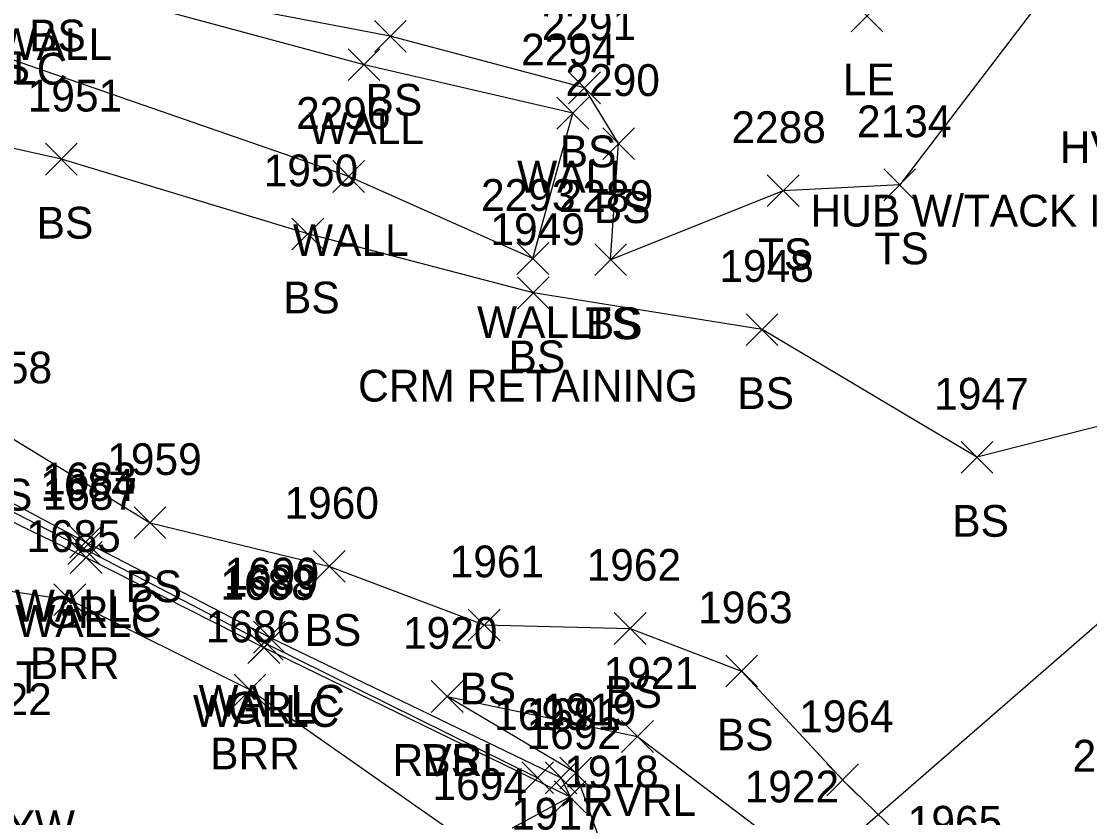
# Model space of a CAD drawing. Extents: x 1647133 to 1649138, y 411736 to 414924.
# Drawn here: x 1648810.3 to 1648877.6, y 412125.5 to 412175.6 of the extents above; entities that cross this region are included whole.
import ezdxf

# ---------------------------------------------------------------- set-up
doc = ezdxf.new("R2010")
doc.units = 0
for name, color, linetype in [('BELB', 7, 'Continuous'), ('C_A', 7, 'Continuous'), ('C_C', 7, 'Continuous'), ('L_A', 7, 'Continuous'), ('L_C', 7, 'Continuous'), ('L_I', 7, 'Continuous'), ('L_TIC', 7, 'Continuous'), ('LABL', 7, 'Continuous'), ('LAWE', 7, 'Continuous'), ('LELB', 7, 'Continuous'), ('LW', 7, 'Continuous'), ('R_A', 7, 'Continuous'), ('R_C', 7, 'Continuous'), ('R_I', 7, 'Continuous'), ('R_TIC', 7, 'Continuous'), ('RGR', 7, 'Continuous'), ('U_A', 7, 'Continuous'), ('U_I', 7, 'Continuous')]:
    doc.layers.add(name, color=color, linetype=linetype)

msp = doc.modelspace()

# ---------------------------------------------------------------- linework, layer by layer
at = {"layer": 'BELB'}
msp.add_lwpolyline([(1648856.366, 412097.638), (1648845.782, 412109.602), (1648891.837, 412149.616), (1648923.124, 412177.419), (1648960.58, 412211.026), (1648974.892, 412224.907)], dxfattribs=at)
at = {"layer": 'L_TIC'}
for points in [[(1648862.557, 412174.929), (1648864.557, 412176.929)], [(1648864.557, 412174.929), (1648862.557, 412176.929)], [(1648832.549, 412173.646), (1648834.549, 412175.646)], [(1648834.549, 412173.646), (1648832.549, 412175.646)], [(1648830.896, 412171.857), (1648832.896, 412173.857)], [(1648832.896, 412171.857), (1648830.896, 412173.857)], [(1648844.777, 412170.401), (1648846.777, 412172.401)], [(1648846.777, 412170.401), (1648844.777, 412172.401)], [(1648844.045, 412168.806), (1648846.045, 412170.806)], [(1648846.045, 412168.806), (1648844.045, 412170.806)], [(1648846.923, 412166.888), (1648848.923, 412168.888)], [(1648848.923, 412166.888), (1648846.923, 412168.888)], [(1648811.843, 412165.91), (1648813.843, 412167.91)], [(1648813.843, 412165.91), (1648811.843, 412167.91)], [(1648829.932, 412164.818), (1648831.932, 412166.818)], [(1648831.932, 412164.818), (1648829.932, 412166.818)], [(1648864.626, 412164.294), (1648866.626, 412166.294)], [(1648866.626, 412164.294), (1648864.626, 412166.294)], [(1648857.285, 412163.924), (1648859.285, 412165.924)], [(1648859.285, 412163.924), (1648857.285, 412165.924)], [(1648827.356, 412161.203), (1648829.356, 412163.203)], [(1648829.356, 412161.203), (1648827.356, 412163.203)], [(1648841.521, 412159.657), (1648843.521, 412161.657)], [(1648843.521, 412159.657), (1648841.521, 412161.657)], [(1648841.521, 412159.657), (1648843.521, 412161.657)], [(1648843.521, 412159.657), (1648841.521, 412161.657)], [(1648846.42, 412159.585), (1648848.42, 412161.585)], [(1648848.42, 412159.585), (1648846.42, 412161.585)], [(1648846.42, 412159.585), (1648848.42, 412161.585)], [(1648848.42, 412159.585), (1648846.42, 412161.585)], [(1648841.553, 412157.499), (1648843.553, 412159.499)], [(1648843.553, 412157.499), (1648841.553, 412159.499)], [(1648855.957, 412155.187), (1648857.957, 412157.187)], [(1648857.957, 412155.187), (1648855.957, 412157.187)], [(1648869.49, 412147.148), (1648871.49, 412149.148)], [(1648871.49, 412147.148), (1648869.49, 412149.148)], [(1648817.426, 412143.032), (1648819.426, 412145.032)], [(1648819.426, 412143.032), (1648817.426, 412145.032)], [(1648813.37, 412141.815), (1648815.37, 412143.815)], [(1648815.37, 412141.815), (1648813.37, 412143.815)], [(1648813.399, 412140.844), (1648815.399, 412142.844)], [(1648815.399, 412140.844), (1648813.399, 412142.844)], [(1648828.711, 412140.28), (1648830.711, 412142.28)], [(1648830.711, 412140.28), (1648828.711, 412142.28)], [(1648812.37, 412138.189), (1648814.37, 412140.189)], [(1648814.37, 412138.189), (1648812.37, 412140.189)], [(1648838.461, 412136.596), (1648840.461, 412138.596)], [(1648840.461, 412136.596), (1648838.461, 412138.596)], [(1648847.65, 412136.378), (1648849.65, 412138.378)], [(1648849.65, 412136.378), (1648847.65, 412138.378)], [(1648824.933, 412135.828), (1648826.933, 412137.828)], [(1648826.933, 412135.828), (1648824.933, 412137.828)], [(1648824.589, 412135.181), (1648826.589, 412137.181)], [(1648826.589, 412135.181), (1648824.589, 412137.181)], [(1648854.669, 412133.7), (1648856.669, 412135.7)], [(1648856.669, 412133.7), (1648854.669, 412135.7)], [(1648823.717, 412132.505), (1648825.717, 412134.505)], [(1648825.717, 412132.505), (1648823.717, 412134.505)], [(1648836.128, 412132.097), (1648838.128, 412134.097)], [(1648838.128, 412132.097), (1648836.128, 412134.097)], [(1648836.128, 412132.097), (1648838.128, 412134.097)], [(1648838.128, 412132.097), (1648836.128, 412134.097)], [(1648848.111, 412129.576), (1648850.111, 412131.576)], [(1648850.111, 412129.576), (1648848.111, 412131.576)], [(1648844.222, 412127.283), (1648846.222, 412129.283)], [(1648846.222, 412127.283), (1648844.222, 412129.283)], [(1648843.3, 412126.977), (1648845.3, 412128.977)], [(1648845.3, 412126.977), (1648843.3, 412128.977)], [(1648861.03, 412126.85), (1648863.03, 412128.85)], [(1648863.03, 412126.85), (1648861.03, 412128.85)], [(1648843.864, 412125.782), (1648845.864, 412127.782)], [(1648845.864, 412125.782), (1648843.864, 412127.782)], [(1648843.864, 412125.782), (1648845.864, 412127.782)], [(1648845.864, 412125.782), (1648843.864, 412127.782)], [(1648843.864, 412125.782), (1648845.864, 412127.782)], [(1648845.864, 412125.782), (1648843.864, 412127.782)]]:
    msp.add_lwpolyline(points, dxfattribs=at)
at = {"layer": 'LABL'}
msp.add_lwpolyline([(1648799.847, 412141.142), (1648813.37, 412139.189), (1648824.717, 412133.505), (1648838.944, 412123.578)], dxfattribs=at)
at = {"layer": 'LAWE'}
msp.add_lwpolyline([(1648837.128, 412133.097), (1648849.111, 412130.576), (1648858.551, 412123.429), (1648865.22, 412116.653), (1648885.08, 412098.314), (1648895.742, 412085.318), (1648904.966, 412074.676), (1648913.662, 412064.354), (1648932.191, 412046.181), (1648949.069, 412033.32)], dxfattribs=at)
at = {"layer": 'LELB'}
for points in [[(1648866.333, 412278.881), (1648876.088, 412276.418), (1648879.49, 412267.934), (1648882.681, 412258.794), (1648883.567, 412248.769), (1648885.154, 412240.422), (1648883.591, 412228.327), (1648886.596, 412217.634), (1648887.939, 412203.276), (1648883.632, 412188.867), (1648865.626, 412165.294), (1648858.285, 412164.924), (1648847.42, 412160.585)], [(1648847.42, 412160.585), (1648847.923, 412167.888), (1648845.777, 412171.401), (1648833.549, 412174.646), (1648812.367, 412178.69)], [(1648885.787, 412152.041), (1648870.49, 412148.148), (1648856.957, 412156.187), (1648842.553, 412158.499), (1648828.356, 412162.203), (1648812.843, 412166.91), (1648807.082, 412168.189), (1648801.769, 412172.895), (1648797.645, 412167.837), (1648792.644, 412160.569), (1648799.379, 412154.937), (1648809.001, 412149.8), (1648818.426, 412144.032), (1648829.711, 412141.28), (1648839.461, 412137.596), (1648848.65, 412137.378), (1648855.669, 412134.7), (1648862.03, 412127.85), (1648868.869, 412121.213), (1648875.311, 412117.612), (1648882.604, 412109.86)], [(1648843.282, 412121.718), (1648846.627, 412124.369), (1648845.222, 412128.283), (1648837.128, 412133.097)], [(1648844.864, 412126.782), (1648838.944, 412123.578)]]:
    msp.add_lwpolyline(points, dxfattribs=at)
at = {"layer": 'LW'}
for points in [[(1648842.521, 412160.657), (1648845.045, 412169.806), (1648831.896, 412172.857), (1648812.267, 412178.152)], [(1648842.521, 412160.657), (1648830.932, 412165.818), (1648805.688, 412174.564)], [(1648787.891, 412144.427), (1648782.709, 412152.826), (1648792.342, 412158.855), (1648800.309, 412150.294), (1648814.37, 412142.815), (1648825.933, 412136.828), (1648844.3, 412127.977), (1648844.864, 412126.782)], [(1648787.891, 412144.427), (1648788.377, 412144.745), (1648784.217, 412151.553), (1648787.27, 412153.379), (1648787.94, 412152.444), (1648793.992, 412154.764), (1648799.503, 412149.051), (1648814.399, 412141.844), (1648825.589, 412136.181), (1648844.864, 412126.782)]]:
    msp.add_lwpolyline(points, dxfattribs=at)
at = {"layer": 'R_TIC'}
for points in [[(1648813.25, 412141.408), (1648815.25, 412143.408)], [(1648815.25, 412141.408), (1648813.25, 412143.408)], [(1648824.804, 412135.387), (1648826.804, 412137.387)], [(1648826.804, 412135.387), (1648824.804, 412137.387)], [(1648841.827, 412126.982), (1648843.827, 412128.982)], [(1648843.827, 412126.982), (1648841.827, 412128.982)]]:
    msp.add_lwpolyline(points, dxfattribs=at)
at = {"layer": 'RGR'}
msp.add_lwpolyline([(1648792.303, 412158.164), (1648799.95, 412149.784), (1648814.25, 412142.408), (1648825.804, 412136.387), (1648842.827, 412127.982)], dxfattribs=at)

# ---------------------------------------------------------------- texts
at = {"layer": 'C_A'}
msp.add_text('HVCTRL', height=2, dxfattribs=at).set_placement((1648875.707, 412166.671))
at = {"layer": 'C_C'}
msp.add_text('HUB W/TACK IN DRILL HOLE', height=2, dxfattribs=at).set_placement((1648860.006, 412162.671))
at = {"layer": 'L_A'}
for s, p in [('BS', (1648810.808, 412173.69)), ('WALL', (1648808.755, 412173.152)), ('WALLC', (1648804.002, 412171.6)), ('BS', (1648807.3, 412171.673)), ('LE', (1648862.045, 412170.929)), ('BS', (1648831.99, 412169.646)), ('WALL', (1648828.384, 412167.857)), ('BS', (1648844.218, 412166.401)), ('WALL', (1648841.533, 412164.806)), ('BS', (1648846.364, 412162.888)), ('BS', (1648811.283, 412161.91)), ('WALL', (1648827.421, 412160.818)), ('TS', (1648864.035, 412160.294)), ('TS', (1648856.695, 412159.924)), ('BS', (1648826.797, 412157.203)), ('WALL', (1648839.009, 412155.657)), ('WALL', (1648839.009, 412155.657)), ('TS', (1648845.83, 412155.585)), ('BS', (1648845.861, 412155.585)), ('BS', (1648840.994, 412153.499)), ('BS', (1648855.398, 412151.187)), ('BS', (1648807.442, 412144.8)), ('BS', (1648868.931, 412143.148)), ('BS', (1648816.867, 412139.032)), ('WALLC', (1648809.905, 412137.815)), ('WALLC', (1648809.934, 412136.844)), ('BS', (1648828.152, 412136.28)), ('BRR', (1648810.858, 412134.189)), ('BS', (1648837.902, 412132.596)), ('BS', (1648847.091, 412132.378)), ('WALLC', (1648821.468, 412131.828)), ('WALLC', (1648821.125, 412131.181)), ('BS', (1648854.11, 412129.7)), ('BRR', (1648822.205, 412128.505)), ('RVRL', (1648833.695, 412128.097)), ('BS', (1648835.569, 412128.097)), ('RVRL', (1648845.678, 412125.576))]:
    msp.add_text(s, height=2, dxfattribs=at).set_placement(p)
at = {"layer": 'L_C'}
msp.add_text('CRM RETAINING', height=2, dxfattribs=at).set_placement((1648831.521, 412151.657))
msp.add_text('CRM RETAINING', height=2, dxfattribs=at).set_placement((1648831.521, 412151.657))
at = {"layer": 'L_I'}
for s, p in [('2291', (1648843.084, 412174.401)), ('2294', (1648841.785, 412172.806)), ('2290', (1648844.577, 412170.888)), ('1951', (1648810.717, 412169.91)), ('2296', (1648827.617, 412168.818)), ('2134', (1648862.933, 412168.294)), ('2288', (1648855.026, 412167.924)), ('1950', (1648825.577, 412165.203)), ('2293', (1648839.261, 412163.657)), ('2293', (1648839.261, 412163.657)), ('2289', (1648844.153, 412163.585)), ('2289', (1648844.153, 412163.585)), ('1949', (1648839.852, 412161.499)), ('1948', (1648854.264, 412159.187)), ('1958', (1648806.308, 412152.8)), ('1947', (1648867.797, 412151.148)), ('1959', (1648815.725, 412147.032)), ('1683', (1648811.629, 412145.815)), ('1687', (1648811.659, 412144.844)), ('1960', (1648826.884, 412144.28)), ('1685', (1648810.63, 412142.189)), ('1961', (1648837.288, 412140.596)), ('1962', (1648845.909, 412140.378)), ('1690', (1648823.106, 412139.828)), ('1688', (1648822.849, 412139.181)), ('1963', (1648852.929, 412137.7)), ('1686', (1648821.922, 412136.505)), ('1920', (1648834.349, 412136.097)), ('1920', (1648834.349, 412136.097)), ('1921', (1648846.985, 412133.576)), ('1919', (1648843.088, 412131.283)), ('1691', (1648842.127, 412130.977)), ('1964', (1648859.29, 412130.85)), ('1692', (1648842.124, 412129.782)), ('1692', (1648842.124, 412129.782)), ('1692', (1648842.124, 412129.782)), ('2311', (1648876.509, 412128.367)), ('1918', (1648844.501, 412127.369)), ('1694', (1648836.203, 412126.578)), ('1694', (1648836.203, 412126.578)), ('1694', (1648836.203, 412126.578)), ('1922', (1648855.858, 412126.429)), ('1917', (1648841.156, 412124.718)), ('1965', (1648866.129, 412124.213))]:
    msp.add_text(s, height=2, dxfattribs=at).set_placement(p)
at = {"layer": 'R_A'}
for p in [(1648811.793, 412137.408), (1648823.348, 412131.387)]:
    msp.add_text('GRL', height=2, dxfattribs=at).set_placement(p)
at = {"layer": 'R_C'}
msp.add_text('STEEL GATE POST', height=2, dxfattribs=at).set_placement((1648787.067, 412133.301))
at = {"layer": 'R_I'}
for s, p in [('1684', (1648811.51, 412145.408)), ('1689', (1648823.056, 412139.387)), ('1693', (1648840.087, 412130.982))]:
    msp.add_text(s, height=2, dxfattribs=at).set_placement(p)
at = {"layer": 'U_A'}
msp.add_text('GUYW', height=2, dxfattribs=at).set_placement((1648805.369, 412123.925))
at = {"layer": 'U_I'}
msp.add_text('1522', height=2, dxfattribs=at).set_placement((1648806.282, 412131.925))

doc.saveas('drawing.dxf')
